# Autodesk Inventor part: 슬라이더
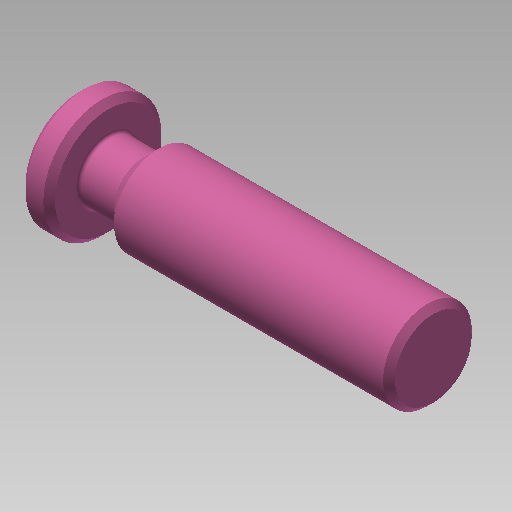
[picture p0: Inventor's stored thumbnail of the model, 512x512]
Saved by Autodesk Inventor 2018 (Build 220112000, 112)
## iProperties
Created: 2016-05
Part Number: 슬라이더
Document SubType Name: Modeling
Designer: mduedu
Density: 7.86 g/cm^3
Material: 강철, 연강
Appearance: 분홍색
Author: mduedu
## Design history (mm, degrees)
sketch "스케치1"
  geometry: L1 (-7.5, 0)-(52.5, 0); L2 (52.5, 0)-(52.5, 7.5); L3 (52.5, 7.5)-(0, 7.5); L4 (-7.5, 0)-(-7.5, 10); L5 (-7.5, 10)-(-2.5, 10); L6 (-2.5, 10)-(-2.5, 5); L7 (-2.5, 5)-(3.5, 5); L8 (3.5, 5)-(6, 7.5); A1 r 7.5 centre (0, 0) between (0, 7.5) and (-7.5, 0); 1 further point
  constraints: 16 end point, 3 perpendicular, 2 horizontal, 2 parallel, 2 point on circle, 2 point on line, 2 tangent, 1 centre point, 1 coincident
  dimensions: "d0" = 15 diameter of A1; "d1" = 60 distance of L1.start L1.end; "d19" = 20 diameter of L5 L1; "d20" = 10 diameter of L7 L1; "d21" = 5 distance of L4.end L5.end; "d22" = 135 deg angle of L8 L7; "d23" = 6 distance of L6.end L7.end
revolve "회전1" stored, may be unused: angle "d4" = 90 deg
chamfer "모따기2" distance "d24" = 1; stored, may be unused: second distance "d25" = 2, angle "d26" = 45 deg
fillet "모깎기1" dims "d27" = 0.5
node "솔리드1"
